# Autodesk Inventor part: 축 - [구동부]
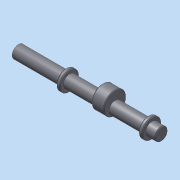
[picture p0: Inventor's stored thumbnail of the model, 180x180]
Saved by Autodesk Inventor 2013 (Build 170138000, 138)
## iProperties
Company: 한국ATC센터
Created: 2014-08
Part Number: 축 - [구동부]
Document SubType Name: Modeling
Designer: KYOUNG IL JANG
Density: 7.86 g/cm^3
Material: 강, 연강
Mass: 427.957 g
Surface Area: 136.7 cm^2
Volume: 54.4474 cm^3
Author: KYOUNG IL JANG
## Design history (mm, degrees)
sketch "스케치1"
  geometry: L1 (-96.5, 0)-(96.5, 0); L2 (-96.5, 0)-(-96.5, 8.5); L3 (-96.5, 8.5)-(-32.5, 8.5); L4 (-32.5, 8.5)-(-32.5, 13); L5 (-32.5, 13)-(-27.5, 13); L6 (-27.5, 13)-(-27.5, 8.5); L7 (-27.5, 8.5)-(78.5, 8.5); L8 (78.5, 8.5)-(78.5, 13); L9 (78.5, 13)-(83.5, 13); L10 (83.5, 13)-(83.5, 8.5); L11 (83.5, 8.5)-(96.5, 8.5); L12 (96.5, 8.5)-(96.5, 0); 2 further points
  constraints: 24 end point, 5 parallel, 1 coincident, 1 horizontal, 1 midpoint, 1 perpendicular
  dimensions: "d0" = 193 distance of L1.start L1.end (derived); "d2" = 17 diameter of L3 L1; "d3" = 26 diameter of L5 L1; "d4" = 17 diameter of L7 L1; "d5" = 26 diameter of L9 L1; "d6" = 17 diameter of L11 L1; "d7" = 5 distance of L8.end L9.end; "d8" = 5 distance of L4.end L5.end; "d10" = 64 distance of L2.end L3.end; "d11" = 13 distance of L10.end L11.end; "d35" = 106 distance between parallel lines of L8 L6
revolve "회전1" sketch "스케치1" stored, may be unused: angle "d12" = 90 deg
node "작업 평면1"
node "작업 평면2"
node "작업 평면4"
sketch "스케치6"
  geometry: C1 r 15 at (-5, -6); 1 further point
  constraints: 1 centre point, 1 horizontal alignment
  dimensions: "d31" = 30 diameter of C1; "d32" = 5 distance of C1.centre point (0, -6)
extrude "돌출4" join sketch "스케치6" stored distance "d33" = 17; taper "d34" = 0 deg
node "작업 평면3"
sketch "스케치5"
  geometry: L1 (32, 8.5)-(32, -8.5) reference; L2 (32, -2.5)-(14.5, -2.5); L3 (14.5, 2.5)-(32, 2.5); A1 r 2.5 centre (14.5, 0) between (14.5, 2.5) and (14.5, -2.5); 2 further points
  constraints: 4 end point, 2 point on circle, 2 point on line, 2 tangent, 1 centre point, 1 midpoint, 1 parallel, 1 perpendicular
  dimensions: "d23" = 5 distance between parallel lines of L3 L2; "d36" = 20 dimension on A1 L1
extrude "돌출3" cut sketch "스케치5" distance "d25" = 3; taper "d26" = 0 deg
chamfer "모따기1" distance "d27" = 1; stored, may be unused: second distance "d28" = 2, angle "d29" = 45 deg
node "솔리드1"
other parameters: "d13" = 9.5, "d18" = 9.5
